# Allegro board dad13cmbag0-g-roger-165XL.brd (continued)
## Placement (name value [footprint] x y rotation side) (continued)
PR73  620k/f_4  [RC0402]  116.67 40.9 270 top
PR74  100k_4  [RC0402]  134.83 40.75 0 top
PR75  *0_4_nc  [RC0402]  118.2 40.39 180 top
PR76  *sj0805_nc  [SHORT0805]  163.03 40.21 270 top
PR77  100k/f_4  [RC0402]  125.05 40.09 180 top
PR78  0_6  [RC0603]  146.84 39.7 0 top
PR79  0_6  [RC0603]  155.86 39.7 180 top
PR80  147k/f_4  [RC0402]  137.55 38.94 270 top
PR81  17.4k/f_4  [RC0402]  128.56 38.56 90 top
PR82  *sj0402_nc  [SHORT0402]  115.28 38.36 90 top
PR83  *sj0402_nc  [SHORT0402]  116.29 38.36 270 top
PR84  10k/f_4  [RC0402]  192.19 37.34 270 top
PR86  *sj0402_nc  [SHORT0402]  125.94 35.89 90 top
PR87  *sj0402_nc  [SHORT0402]  126.96 35.89 90 top
PR88  35.7k/f_4  [RC0402]  128.99 35.89 270 top
PR89  220k/f_4  [RC0402]  131.02 35.89 90 top
PR90  71.5k/f_4  [RC0402]  115.78 35.82 180 top
PR91  *sj0603_nc  [SHORT0603]  122.97 35.51 270 top
PR92  *sj0603_nc  [SHORT0603]  149.18 34.75 270 top
PR93  11.5k/f_4  [RC0402]  191.65 34.5 0 top
PR94  *sj0402_nc  [SHORT0402]  164.91 34.24 90 top
PR95  *10k_4_nc  [RC0402]  165.92 34.09 90 top
PR96  10k_4  [RC0402]  168.11 34.24 90 top
PR98  12.4k/f_4  [RC0402]  132.42 34.12 180 top
PR100  4.02k/f_4  [RC0402]  124.29 33.35 0 top
PR101  10k/f_4  [RC0402]  191.65 33.33 180 top
PR102  10k/f_4  [RC0402]  132.42 33.1 0 top
PR103  20k/f_4  [RC0402]  113.8 33.08 0 top
PR104  0_6  [RC0603]  119.39 32.52 90 top
PR105  4.7k_4  [RC0402]  132.42 31.83 0 top
PR106  20k/f_4  [RC0402]  114.31 31.45 90 top
PR107  *sj0805_nc  [SHORT0805]  95.46 31.32 270 top
PR108  *2.2_8_nc  [RC0805]  140.65 31.14 270 top
PR109  *2.2_8_nc  [RC0805]  160.61 31.07 270 top
PR110  *sj0402_nc  [SHORT0402]  189.89 29.46 270 top
PR111  10k_4  [RC0402]  190.9 29.46 270 top
PR112  10k_4  [RC0402]  192.93 29.46 270 top
PR113  *sj0402_nc  [SHORT0402]  193.95 29.46 90 top
PR114  *10k_4_nc  [RC0402]  98.89 28.4 270 top
PR115  *sj0402_nc  [SHORT0402]  99.91 28.4 270 top
PR116  0_6  [RC0603]  127.31 27.18 90 top
PR117  *sj0805_nc  [SHORT0805]  92.8 27.13 0 top
PR118  *2.2_8_nc  [RC0805]  112.76 26.67 0 top
PR119  10_12  [RC1206]  131.56 25.61 270 top
PR120  *sj0402_nc  [SHORT0402]  198.59 23.45 0 top
PR121  4.02k/f_4  [RC0402]  120.61 19.77 90 top
PR123  *100k_4_nc  [RC0402]  198.59 22.43 0 top
PR124  10k_4  [RC0402]  9.23 23.07 90 top
PR125  *100k_4_nc  [RC0402]  198.59 18.37 0 top
PR127  *sj0805_nc  [SHORT0805]  173.82 18.11 180 top
PR128  *sj0402_nc  [SHORT0402]  198.59 17.35 0 top
PR129  *sj0805_nc  [SHORT0805]  165.95 16.84 0 top
PR130  200k_4  [RC0402]  133.36 16.49 180 top
PR131  *10k_4_nc  [RC0402]  10.25 23.07 90 top
PR132  2.2_8  [RC0805]  127.62 14.99 0 top
PR133  10k_4  [RC0402]  108.16 14.41 180 top
PR134  10k_4  [RC0402]  110.2 14.41 0 top
PR135  15k_4  [RC0402]  4.02 14.33 0 top
PR136  10k_4  [RC0402]  2.32 13.7 90 top
PR137  100k_4  [RC0402]  4.02 13.19 0 top
PR138  100_4  [RC0402]  112.23 12.91 270 top
PR139  100_4  [RC0402]  113.62 12.91 270 top
PR140  100_4  [RC0402]  107.66 12.88 270 top
PR141  100_4  [RC0402]  110.7 12.88 270 top
PR142  10k_4  [RC0402]  132.39 12.65 180 top
PR143  *sj0402_nc  [SHORT0402]  168.34 11.69 90 top
PR144  *10k_4_nc  [RC0402]  169.48 11.69 90 top
PR145  10k_4  [RC0402]  171.64 11.69 90 top
PR146  *sj0402_nc  [SHORT0402]  172.78 11.69 270 top
PR147  680k_4  [RC0402]  135.34 9.48 90 top
PR148  2.2k_4  [RC0402]  5.9 8.46 90 top
PR149  33_4  [RC0402]  4.33 8.44 180 top
PR150  100k_4  [RC0402]  133.66 7.14 180 top
PR151  47k_4  [RC0402]  157.31 65.23 270 bottom
PR152  240k_4  [RC0402]  158.33 65.23 90 bottom
PR155  5.76k/f_4  [RC0402]  28.28 63.33 270 bottom
PR156  *sj0402_nc  [SHORT0402]  183.25 63.17 180 bottom
PR157  *sj0201_nc  [SHORT0201]  88.12 62.31 90 bottom
PR158  *sj0201_nc  [SHORT0201]  89.06 62.31 90 bottom
PR160  10k/f_4  [RC0402]  28.79 61.8 180 bottom
PR161  300k/f_4  [RC0402]  186.9 61.55 270 bottom
PR162  *10k/f_4_nc  [RC0402]  188.05 61.55 90 bottom
PR163  *10k/f_4_nc  [RC0402]  189.19 61.55 90 bottom
PR164  10k/f_4  [RC0402]  190.33 61.55 90 bottom
PR165  10k/f_4  [RC0402]  21.68 61.42 90 bottom
PR166  *sj0402_nc  [SHORT0402]  24.98 61.42 270 bottom
PR167  *sj0402_nc  [SHORT0402]  26.12 61.42 270 bottom
PR168  *sj0603_nc  [SHORT0603]  109.79 61.35 0 bottom
PR169  10k/f_4  [RC0402]  19.64 60.79 0 bottom
PR170  2.49k/f_4  [RC0402]  28.79 59.77 180 bottom
PR171  0_6  [RC0603]  101.71 58.37 90 bottom
PR172  100k/ntc/b4250_4  [RC0402]  17.99 58.12 270 bottom
PR173  *sj0402_nc  [SHORT0402]  103.46 57.99 90 bottom
PR174  *sj0402_nc  [SHORT0402]  104.48 57.99 90 bottom
PR175  *0_4_nc  [RC0402]  105.5 57.99 270 bottom
PR176  2.2_6  [RC0603]  15.83 57.94 270 bottom
PR177  *562k/f_4_nc  [RC0402]  19.64 57.74 180 bottom
PR178  499k/f_4  [RC0402]  19.64 56.72 180 bottom
PR179  *sj0402_nc  [SHORT0402]  28.94 56.6 0 bottom
PR180  9.31k/f_4  [RC0402]  19.57 55.71 180 bottom
PR181  *sj0402_nc  [SHORT0402]  28.94 55.45 0 bottom
PR182  150k/f_4  [RC0402]  19.64 54.69 0 bottom
PR183  *sj0402_nc  [SHORT0402]  28.94 54.31 0 bottom
PR184  2.94k/f_4  [RC0402]  19.64 53.67 180 bottom
PR185  *sj0402_nc  [SHORT0402]  22.44 52.28 270 bottom
PR186  *sj0402_nc  [SHORT0402]  23.45 52.28 270 bottom
PR187  *0_4_nc  [RC0402]  24.47 52.4 90 bottom
PR188  1k_4  [RC0402]  25.49 52.4 90 bottom
PR189  *sj0402_nc  [SHORT0402]  27.52 52.4 270 bottom
PR190  130_4  [RC0402]  28.53 52.4 270 bottom
PR191  *sj0402_nc  [SHORT0402]  30.95 52.4 270 bottom
PR192  1.91k/f_4  [RC0402]  18.12 52.15 270 bottom
PR193  18.7k/f_4  [RC0402]  19.14 52.15 90 bottom
PR194  10k/ntc/b3900_4  [RC0402]  20.15 52.15 270 bottom
PR196  2.2_8  [RC0805]  8.87 45.5 0 bottom
PR198  *sj0402_nc  [SHORT0402]  94.73 33.48 90 bottom
PR199  *100k_4_nc  [RC0402]  95.74 33.48 90 bottom
PR202  *sj0402_nc  [SHORT0402]  105.24 31.2 90 bottom
PR204  100k/f_4  [RC0402]  152.11 26.01 0 bottom
PR207  137k/f_4  [RC0402]  147.91 25.35 90 bottom
PR208  1.5m_4  [RC0402]  155.28 24.72 180 bottom
PR210  0.01_0612  [RC3216-4P]  127.72 22.13 270 bottom
PR211  0.01_0612  [RC3216-4P]  122.56 14.1 0 bottom
PR212  *0_4_nc  [RC0402]  181.57 13.16 90 bottom
PR213  *sj0402_nc  [SHORT0402]  182.97 13.16 270 bottom
PR214  51.1k/f_4  [RC0402]  185.51 12.65 0 bottom
PR215  102k/f_4  [RC0402]  187.54 11.51 0 bottom
PR218  75k/f_4  [RC0402]  128.99 45.67 90 top
PR219  100k_4  [RC0402]  152.74 24.21 270 top
PR220  *0_4_nc  [RC0402]  7.33 22.56 0 top
PR221  *sj0402_nc  [SHORT0402]  177 65.28 180 top
PR222  100k_4  [RC0402]  6.18 16.59 270 top
PR223  *sj0402_nc  [SHORT0402]  177.25 66.35 180 top
PR224  *sj0402_nc  [SHORT0402]  176.74 64.27 180 top
PR225  *sj0402_nc  [SHORT0402]  178.78 66.63 90 top
PR226  *sj0402_nc  [SHORT0402]  46.82 65.99 180 top
PR227  *0_4_nc  [RC0402]  102.96 31.2 270 bottom
PR228  *sj0402_nc  [SHORT0402]  104.1 31.2 90 bottom
PR229  *sj0402_nc  [SHORT0402]  58 27.13 270 bottom
PR230  *sj0402_nc  [SHORT0402]  126.2 45.93 90 top
PR231  *100k_4_nc  [RC0402]  122.9 21.92 270 top
PR232  *sj0402_nc  [SHORT0402]  169.12 34.24 270 top
PU1  oz9955hln  [QFN24-4X4-5-25P-0_8H]  181.37 62.44 180 top
PU2  tps22966dpur  [SON14-3X2-4-15P]  99.65 50.25 0 top
PU3  tps22966dpur  [SON14-3X2-4-15P]  123.12 49.1 0 top
PU4  tps22965dsgr  [SON8-2X2-5-9P]  160.61 45.93 90 top
PU5  tps22966dpur  [SON14-3X2-4-15P]  190.33 44.66 0 top
PU6  azv331ktr-g1  [SOT23-5]  129.75 41.48 270 top
PU7  rt8230cgqw  [WQFN20-3X3-4-21P]  151.37 39.04 270 top
PU8  nl27wz00usg  [VSSOP8-3_1-5-8P-0_9H]  133.56 38.82 270 top
PU9  tps22966dpur  [SON14-3X2-4-15P]  166.31 37.78 0 top
PU10  rt8231agqw  [WQFN20-3X3-4-21P]  119.44 36.96 180 top
PU11  g9661-25adjtp1u  [TSOT23-6-2_8-95-6P-1H]  195.39 35.41 90 top
PU12  bq24715rgrr  [PVQFN20-3_5X3_5-5-25P]  128.25 31.68 90 top
PU13  tps22966dpur  [SON14-3X2-4-15P]  96.38 27.74 90 top
PU14  tps22966dpur  [SON14-3X2-4-15P]  191.31 26.1 180 top
PU15  tps22966dpur  [SON14-3X2-4-15P]  202.02 20.38 270 top
PU16  tps22966dpur  [SON14-3X2-4-15P]  170.54 15.37 0 top
PU17  tps51362rver  [QFN28-4_5X3_5-4-29P]  105.52 62.49 90 bottom
PU18  tps51622arsmr  [QFN32-4X4-4-42P-1H]  24.22 56.98 90 bottom
PU19  *tps22965dsgr_nc  [SON8-2X2-5-9P]  94.24 35.87 270 bottom
PU20  azv331ktr-g1  [SOT23-5]  152.26 23.65 180 bottom
PU21  rt8068azqw  [DFN10-3X3-5-11P-RT9296]  183.8 10.32 90 bottom
PV1  fbd13021010  [SPAD-RE95X87]  45.91 30.2 180 bottom
PV2  *fbkt200401_nc  [SPAD-RE95X87]  54.91 30.2 180 bottom
Q1  dmn5l06wk-7  [UMT_213-3-1_3]  205.57 65.49 270 top
Q2  2n7002w  [UMT_213-3-1_3]  198.21 65.36 90 top
Q3  2n7002w  [UMT_213-3-1_3]  144.36 64.98 270 top
Q4  dmn66d0ldw-7  [SOT-363]  128.86 61.17 270 top
Q5  2n7002w  [UMT_213-3-1_3]  122.51 55.2 270 top
Q6  mmst3904-7-f  [UMT_213-3-1_3]  55.2 51.77 0 top
Q7  2n7002w  [UMT_213-3-1_3]  21.57 40.09 180 top
Q8  2n7002w  [UMT_213-3-1_3]  79.72 35.23 180 top
Q9  ao3409  [SOT23_213-3_3-2]  79.59 31.7 90 top
Q13  2n7002w  [UMT_213-3-1_3]  180.43 24.72 270 top
Q14  2n7002w  [UMT_213-3-1_3]  159.06 22.03 270 top
Q15  lta014yubfs8tl  [UMT_213-3-1_3]  161.88 22.03 270 top
Q16  dmn66d0ldw-7  [SOT-363]  177.45 20.63 180 top
Q17  mmst3904-7-f  [UMT_213-3-1_3]  13.17 19.64 0 top
Q18  2n7002w  [UMT_213-3-1_3]  183.6 19.64 270 top
Q19  *ao3409_nc  [SOT23_213-3_3-2]  102.96 15.7 270 top
Q20  2n7002w  [UMT_213-3-1_3]  219.29 14.2 180 top
Q21  fdn357n  [SOT23_213-3_3-2]  177.23 13.59 180 top
Q22  *2n7002w_nc  [UMT_213-3-1_3]  99.27 13.16 90 top
Q23  2n7002w  [UMT_213-3-1_3]  42.61 65.87 180 bottom
Q24  *dmn66d0ldw-7_nc  [SOT-363]  91.53 55.45 180 bottom
Q25  dmn66d0ldw-7  [SOT-363]  91.53 53.17 0 bottom
Q26  dmn66d0ldw-7  [SOT-363]  172.17 46.31 180 bottom
Q27  dmn66d0ldw-7  [SOT-363]  178.75 45.67 0 bottom
Q28  dmn66d0ldw-7  [SOT-363]  89.62 44.15 270 bottom
Q29  2n7002w  [UMT_213-3-1_3]  94.09 42.09 270 bottom
Q30  mmst3904-7-f  [UMT_213-3-1_3]  206.33 34.24 90 top
Q31  2n7002w  [UMT_213-3-1_3]  221.42 28.78 90 bottom
Q32  *bss138_nc  [SOT23_213-3_3-2]  169.76 28.62 90 bottom
Q33  2n7002w  [UMT_213-3-1_3]  221.42 24.08 90 bottom
Q34  2n7002w  [UMT_213-3-1_3]  221.42 20.27 90 bottom
Q35  2n7002w  [UMT_213-3-1_3]  220.96 17.1 180 bottom
Q36  2n7002w  [UMT_213-3-1_3]  160.49 8.97 90 bottom
Q37  2n7002w  [UMT_213-3-1_3]  131.33 65.1 90 top
Q38  2n7002w  [UMT_213-3-1_3]  25.28 48.19 90 top
Q39  2n7002w  [UMT_213-3-1_3]  28.1 46.18 270 top
Q40  2n7002w  [UMT_213-3-1_3]  113.77 19.29 90 top
Q41  2n7002w  [UMT_213-3-1_3]  116.62 19.38 270 top
Q42  dmn66d0ldw-7  [SOT-363]  175.22 25.61 0 top
Q43  *dmn66d0ldw-7_nc  [SOT-363]  169.12 25.86 180 top
Q44  *dmn66d0ldw-7_nc  [SOT-363]  169.12 28.15 180 top
R1  150_6  [RC0603]  38.01 66.7 180 top
R2  8.25k/f_4  [RC0402]  70.44 60.02 0 top
R3  *0_4_nc  [RC0402]  207.48 66.25 270 top
R4  100k_4  [RC0402]  208.62 66.25 90 top
R6  10k_4  [RC0402]  140.55 65.82 270 top
R7  10k_4  [RC0402]  138.39 65.87 270 top
R8  1k_4  [RC0402]  172.55 65.49 0 top
R9  4.7k_4  [RC0402]  196.17 65.1 90 top
R10  1m_4  [RC0402]  200.24 65.1 90 top
R11  100k_4  [RC0402]  201.38 65.1 270 top
R12  *100k_4_nc  [RC0402]  202.52 65.1 90 top
R13  10k_4  [RC0402]  129.32 65.28 90 top
R14  1m_4  [RC0402]  203.67 64.72 90 top
R15  *sj0603_nc  [SHORT0603]  133.23 63.96 90 top
R16  *100k_4_nc  [RC0402]  140.55 63.78 270 top
R17  *100k_4_nc  [RC0402]  142.2 63.96 270 top
R18  *0_6_nc  [RC0603]  127.21 63.78 270 top
R19  10k_4  [RC0402]  137.88 63.58 270 top
R20  *sj0402_nc  [SHORT0402]  139.02 63.58 270 top
R21  10k_4  [RC0402]  125.62 62.97 0 top
R22  *0_4_nc  [RC0402]  158.4 63.2 180 top
R23  *sj0402_nc  [SHORT0402]  131.02 62.82 180 top
R25  3k/f_4  [RC0402]  59.65 62.69 180 top
R26  *sj0402_nc  [SHORT0402]  131.02 61.8 180 top
R27  *sj0402_nc  [SHORT0402]  59.65 61.68 0 top
R28  *10k_4_nc  [RC0402]  78.32 60.71 90 top
R30  43_4  [RC0402]  131.4 60.66 0 top
R31  *51/f_4_nc  [RC0402]  41.49 60.41 0 top
R32  100/f_4  [RC0402]  38.95 60.15 270 top
R33  100/f_4  [RC0402]  39.96 60.15 270 top
R34  *100k_4_nc  [RC0402]  76.79 60.15 180 top
R35  3k/f_4  [RC0402]  64.09 59.77 90 top
R36  100k_4  [RC0402]  82.13 59.52 180 top
R37  *sj0402_nc  [SHORT0402]  84.16 59.52 0 top
R38  *sj0402_nc  [SHORT0402]  41.49 59.39 0 top
R39  100k_4  [RC0402]  130.9 59.14 90 top
R40  24.9/f_4  [RC0402]  66.76 58.98 180 top
R41  100k_4  [RC0402]  122.9 57.61 0 top
R42  100k_4  [RC0402]  128.76 58.63 180 top
R43  *1k_4_nc  [RC0402]  82.13 58.5 180 top
R44  *1k_4_nc  [RC0402]  84.16 58.5 0 top
R45  51/f_4  [RC0402]  39.46 58.63 0 top
R46  51/f_4  [RC0402]  41.49 58.37 180 top
R47  10k_4  [RC0402]  120.86 58.4 0 top
R48  4.7k_4  [RC0402]  147.41 58.37 90 top
R49  *sj0402_nc  [SHORT0402]  148.42 58.37 90 top
R50  *sj0402_nc  [SHORT0402]  149.44 58.37 90 top
R51  *sj0402_nc  [SHORT0402]  151.47 58.37 90 top
R52  *sj0402_nc  [SHORT0402]  152.49 58.37 90 top
R53  *sj0402_nc  [SHORT0402]  154.52 58.37 90 top
R54  *sj0402_nc  [SHORT0402]  155.53 58.37 90 top
R55  *sj0402_nc  [SHORT0402]  157.57 58.37 90 top
R56  0_4  [RC0402]  158.58 58.37 90 top
R57  4.7k_4  [RC0402]  159.6 58.37 270 top
R58  *0_4_nc  [RC0402]  160.61 58.37 270 top
R59  100k_4  [RC0402]  194.27 58.25 180 top
R60  0_6  [RC0603]  87.97 57.48 180 top
R62  *sj0603_nc  [SHORT0603]  68.03 56.72 270 top
R63  *sj0603_nc  [SHORT0603]  69.17 56.72 270 top
R64  *0_6_nc  [RC0603]  87.97 56.21 180 top
R65  10k_4  [RC0402]  80.86 55.58 0 top
R66  20k/f_4  [RC0402]  144.61 55.2 180 top
R67  *sj0402_nc  [SHORT0402]  128.1 54.82 90 top
R68  *10k_4_nc  [RC0402]  78.7 54.56 180 top
R69  *sj0402_nc  [SHORT0402]  83.75 54.56 0 top
R71  *100k_4_nc  [RC0402]  201 54.44 180 top
R72  100k_4  [RC0402]  125.31 54.31 0 top
R73  12k/f_4  [RC0402]  144.61 54.18 0 top
R74  10k_4  [RC0402]  187.16 54.18 0 top
R75  *sj0402_nc  [SHORT0402]  126.96 53.8 270 top
R76  *sj0402_nc  [SHORT0402]  196.43 53.8 90 top
R77  *0_4_nc  [RC0402]  197.44 53.8 270 top
R78  10k_4  [RC0402]  78.7 53.55 180 top
R79  *0_4_nc  [RC0402]  83.75 53.55 0 top
R80  *sj0805_nc  [SHORT0805]  185 53.29 90 top
R81  100k_4  [RC0402]  201 53.29 0 top
R82  *sj0603_nc  [SHORT0603]  75.91 53.17 0 top
R83  *1k_4_nc  [RC0402]  37.04 53.04 0 top
R84  10k_4  [RC0402]  85.28 54.06 90 top
R85  *10k_4_nc  [RC0402]  78.22 52.53 180 top
R86  10k_4  [RC0402]  80.25 52.53 0 top
R87  *10k_4_nc  [RC0402]  84.39 52.53 180 top
R88  *1k_4_nc  [RC0402]  37.04 52.02 0 top
R89  100k_4  [RC0402]  118.45 52.02 270 top
R90  *sj0402_nc  [SHORT0402]  73.49 51.54 180 top
R91  10k_4  [RC0402]  78.22 51.52 180 top
R92  8.2k_4  [RC0402]  80.25 51.52 180 top
R93  100k_4  [RC0402]  84.39 51.52 180 top
R94  10k_4  [RC0402]  85.91 51.9 270 top
R95  *sj1206_nc  [SHORT1206]  65.87 50.75 90 top
R96  *1k_4_nc  [RC0402]  38.19 50.63 0 top
R97  10k_4  [RC0402]  78.22 50.5 180 top
R98  10k_4  [RC0402]  84.31 50.5 180 top
R99  *sj0402_nc  [SHORT0402]  134.45 49.86 270 top
R100  10k_4  [RC0402]  80.25 49.48 180 top
R101  1k_4  [RC0402]  38.19 49.36 0 top
R102  *47k_4_nc  [RC0402]  84.31 49.48 0 top
R103  *sj0402_nc  [SHORT0402]  86.34 49.36 180 top
R104  22.6k/f_4  [RC0402]  198.97 48.72 90 top
R105  78.7k/f_4  [RC0402]  199.98 48.72 90 top
R106  *10k_4_nc  [RC0402]  201 48.72 90 top
R107  1m_4  [RC0402]  76.03 48.47 0 top
R108  10k_4  [RC0402]  80.25 48.47 180 top
R109  *1k_4_nc  [RC0402]  36.31 47.76 0 top
R111  *0_4_nc  [RC0402]  156.98 47.71 180 top
R112  *51_4_nc  [RC0402]  34.2 47.65 180 top
R113  10k_4  [RC0402]  80.86 47.45 180 top
R114  10k_4  [RC0402]  84.31 47.32 180 top
R115  *10k_4_nc  [RC0402]  86.34 47.32 0 top
R116  10k_4  [RC0402]  75.65 46.94 270 top
R117  *1k_4_nc  [RC0402]  37.32 46.72 0 top
R118  *sj_4_nc  [SHORT0402]  80.86 46.44 180 top
R119  10k_4  [RC0402]  82.89 46.31 180 top
R120  *1k_4_nc  [RC0402]  74.1 46.18 180 top
R121  *15k_4_nc  [RC0402]  82.89 45.29 180 top
R122  *sj0603_nc  [SHORT0603]  87.08 45.42 90 top
R123  *0_6_nc  [RC0603]  79.21 45.29 0 top
R124  10k_4  [RC0402]  91.53 44.53 90 top
R125  10k_4  [RC0402]  195.16 44.53 180 top
R126  22.6/f_4  [RC0402]  73.62 44.4 90 top
R127  10k_4  [RC0402]  74.64 44.4 90 top
R128  *sj0603_nc  [SHORT0603]  79.21 44.15 0 top
R129  10k_4  [RC0402]  203.54 43.64 0 top
R130  *0_6_nc  [RC0603]  66.63 43.06 180 top
R131  10k_4  [RC0402]  76.92 43.01 180 top
R132  51_4  [RC0402]  37.58 42.98 270 top
R133  51_4  [RC0402]  38.59 42.98 270 top
R134  51_4  [RC0402]  39.61 42.98 270 top
R135  *1k_4_nc  [RC0402]  40.62 42.98 90 top
R136  10k/f_4  [RC0402]  14.92 42.91 180 top
R137  10k/f_4  [RC0402]  17.08 42.91 180 top
R138  33_4  [RC0402]  106 42.75 180 top
R139  22_4  [RC0402]  68.54 42.12 90 top
R140  49.9/f_4  [RC0402]  72.1 42.12 0 top
R141  10k_4  [RC0402]  74.38 41.61 0 top
R142  100k_4  [RC0402]  89.62 41.61 0 top
R143  10k_4  [RC0402]  75.91 41.36 90 top
R144  *10k_4_nc  [RC0402]  76.92 41.36 90 top
R145  *sj0402_nc  [SHORT0402]  77.94 41.36 90 top
R146  *0_6_nc  [RC0603]  104.35 41.36 270 top
R147  100k_4  [RC0402]  200.24 41.36 90 top
R148  49.9/f_4  [RC0402]  72.1 41.1 0 top
R149  200/f_4  [RC0402]  41.11 41.36 0 top
R150  *sj0603_nc  [SHORT0603]  102.68 40.97 90 top
R151  100/f_4  [RC0402]  38.59 40.95 270 top
R152  *sj0402_nc  [SHORT0402]  89.6 40.59 180 top
R153  1m_4  [RC0402]  109.81 40.47 0 top
R154  22_4  [RC0402]  70.06 40.16 180 top
R155  121/f_4  [RC0402]  41.11 40.34 0 top
R156  10k_4  [RC0402]  75.02 39.32 270 top
R157  *100k_4_nc  [RC0402]  76.03 39.32 270 top
R158  22_4  [RC0402]  68.54 39.07 90 top
R159  *0_6_nc  [RC0603]  183.47 38.05 0 top
R160  *sj0402_nc  [SHORT0402]  20.79 37.57 90 top
R161  47k_4  [RC0402]  21.8 37.57 90 top
R162  *100k_4_nc  [RC0402]  184.49 36.91 0 top
R163  100k_4  [RC0402]  74.13 36.53 270 top
R164  *0_4_nc  [RC0402]  156.96 35.72 90 top
R165  1m_4  [RC0402]  82.13 35.49 90 top
R166  100k_4  [RC0402]  71.71 34.5 270 top
R167  *0_4_nc  [RC0402]  72.73 34.5 90 top
R168  *sj0402_nc  [SHORT0402]  74.13 34.5 270 top
R169  10k_4  [RC0402]  101.31 35.01 180 top
R170  *10k_4_nc  [RC0402]  172.43 33.87 0 top
R171  *0_4_nc  [RC0402]  180.3 33.23 180 top
R172  *0_6_nc  [RC0603]  183.98 32.39 0 top
R173  *49.9k/f_4_nc  [RC0402]  180.3 32.17 0 top
R174  47_4  [RC0402]  101.31 31.91 0 top
R175  33_4  [RC0402]  70.09 31.88 0 top
R176  *sj0603_nc  [SHORT0603]  170.27 31.46 0 top
R177  *0_6_nc  [RC0603]  77.07 31.45 90 top
R178  33_4  [RC0402]  68.51 32.39 270 top
R179  20k/f_4  [RC0402]  72.73 31.35 90 top
R180  20k/f_4  [RC0402]  74.41 31.35 90 top
R181  *100k_4_nc  [RC0402]  184.62 31.25 0 top
R182  *1k_4_nc  [RC0402]  70.09 30.84 0 top
R183  10k_4  [RC0402]  172.81 30.69 180 top
R184  *49.9k/f_4_nc  [RC0402]  180.3 30.27 0 top
R185  *sj0603_nc  [SHORT0603]  177.63 30.01 180 top
R186  *49.9k/f_4_nc  [RC0402]  180.3 29.25 0 top
R187  *sj0402_nc  [SHORT0402]  168.23 32.08 270 top
R188  *sj0402_nc  [SHORT0402]  102.58 28.45 0 top
R189  *0_4_nc  [RC0402]  103.59 28.45 0 top
R190  *sj0402_nc  [SHORT0402]  104.61 28.45 0 top
R191  *100k_4_nc  [RC0402]  176.87 28.36 270 top
R192  *49.9k/f_4_nc  [RC0402]  180.3 28.24 0 top
R193  *0_4_nc  [RC0402]  168.49 30.31 180 top
R194  *sj0402_nc  [SHORT0402]  102.58 27.39 0 top
R195  *0_4_nc  [RC0402]  103.59 27.39 0 top
R196  *sj0402_nc  [SHORT0402]  104.61 27.39 0 top
R197  *sj0402_nc  [SHORT0402]  102.58 26.37 0 top
R198  *0_4_nc  [RC0402]  103.59 26.37 0 top
R199  *sj0402_nc  [SHORT0402]  104.61 26.37 0 top
R200  10k_4  [RC0402]  177.25 23.96 180 top
R201  *sj0805_nc  [SHORT0805]  195.16 25.61 270 top
R202  *sj0402_nc  [SHORT0402]  102.58 25.35 0 top
R203  *0_4_nc  [RC0402]  103.59 25.35 0 top
R204  *sj0402_nc  [SHORT0402]  104.61 25.35 0 top
R205  *0_4_nc  [RC0402]  183.09 25.1 180 top
R206  620_4  [RC0402]  222.59 25.1 90 top
R207  10k_4  [RC0402]  158.71 24.46 180 top
R208  150_4  [RC0402]  162.14 24.46 180 top
R209  *sj0402_nc  [SHORT0402]  102.58 24.34 0 top
R210  *0_4_nc  [RC0402]  103.59 24.34 0 top
R211  *sj0402_nc  [SHORT0402]  104.61 24.34 0 top
R212  100k_4  [RC0402]  183.09 24.08 180 top
R213  *0_4_nc  [RC0402]  177.76 25.99 90 top
R214  *sj0805_nc  [SHORT0805]  188.43 23.45 90 top
R215  10k_4  [RC0402]  183.09 23.07 180 top
R216  10k_4  [RC0402]  183.09 22.05 180 top
R217  620_4  [RC0402]  222.59 21.54 90 top
R218  *0_4_nc  [RC0402]  180.5 21.26 180 top
R219  *0_4_nc  [RC0402]  187.72 21.16 180 top
R220  *0_8_nc  [RC0805]  173.7 20.15 180 top
R221  *0_4_nc  [RC0402]  187.72 20.15 180 top
R222  *0_4_nc  [RC0402]  180.5 19.99 180 top
R223  100k_4  [RC0402]  190.33 19.89 90 top
R224  *0_4_nc  [RC0402]  187.72 19.13 180 top
R225  26.1/f_4  [RC0402]  35.19 19.23 180 top
R226  *0_8_nc  [RC0805]  165.95 18.93 0 top
R227  *0_4_nc  [RC0402]  187.72 18.11 180 top
R228  26.1/f_4  [RC0402]  35.19 18.22 180 top
R229  620_4  [RC0402]  222.59 17.99 90 top
R230  34.8/f_4  [RC0402]  85.3 14.05 270 top
R231  *0_4_nc  [RC0402]  187.72 17.1 180 top
R232  10k_4  [RC0402]  220.94 17.1 0 top
R233  26.1/f_4  [RC0402]  78.62 19.08 0 top
R234  26.1/f_4  [RC0402]  78.62 17.96 0 top
R235  34.8/f_4  [RC0402]  78.57 15.57 90 top
R236  34.8/f_4  [RC0402]  39.08 15.96 270 top
R237  240/f_4  [RC0402]  58.89 16.08 180 top
R238  *0_4_nc  [RC0402]  187.67 16.08 180 top
R239  34.8/f_4  [RC0402]  32.55 16.72 180 top
R240  *0_4_nc  [RC0402]  187.67 15.07 180 top
R241  620_4  [RC0402]  222.46 14.81 90 top
R242  240/f_4  [RC0402]  12.38 14.28 90 top
R243  620_4  [RC0402]  222.08 13.16 180 top
R244  30_4  [RC0402]  18.91 13.03 90 top
R245  *100k_4_nc  [RC0402]  102.96 13.03 0 top
R246  *100k_4_nc  [RC0402]  101.18 12.53 90 top
R247  30_4  [RC0402]  61.99 12.43 90 top
R248  240/f_4  [RC0402]  44.92 9.35 270 top
R249  240/f_4  [RC0402]  22.87 10.75 270 top
R250  240/f_4  [RC0402]  89.49 10.24 270 top
R251  240/f_4  [RC0402]  68.92 9.22 180 top
R252  240/f_4  [RC0402]  72.17 7.62 0 top
R253  1k_4  [RC0402]  46.16 67.01 0 bottom
R254  3k/f_4  [RC0402]  73.62 65.49 270 bottom
R255  10k_4  [RC0402]  39.35 66.25 90 bottom
R257  *0_4_nc  [RC0402]  151.72 65.87 180 bottom
R258  *0_4_nc  [RC0402]  51.01 65.74 270 bottom
R259  *0_4_nc  [RC0402]  52.03 65.74 270 bottom
R260  1m_4  [RC0402]  65.62 65.74 270 bottom
R261  10k_4  [RC0402]  44.94 65.49 90 bottom
R262  10k_4  [RC0402]  46.34 65.49 270 bottom
R263  *sj0402_nc  [SHORT0402]  74.64 65.49 90 bottom
R264  *sj0402_nc  [SHORT0402]  151.72 64.72 0 bottom
R265  *100k/f_4_nc  [RC0402]  83.14 59.26 180 bottom
R266  10k_4  [RC0402]  85.18 59.26 0 bottom
R267  *10k_4_nc  [RC0402]  87.97 58.12 180 bottom
R268  *10k_4_nc  [RC0402]  83.14 58.25 180 bottom
R269  10k_4  [RC0402]  87.97 59.14 180 bottom
R270  10k_4  [RC0402]  83.27 56.37 180 bottom
R271  *1k_4_nc  [RC0402]  90 58.12 180 bottom
R272  *1k_4_nc  [RC0402]  92.03 58.12 0 bottom
R273  10k_4  [RC0402]  87.97 57.1 0 bottom
R274  *10k_4_nc  [RC0402]  90 57.1 180 bottom
R275  *10k_4_nc  [RC0402]  92.03 57.1 180 bottom
R276  10k_4  [RC0402]  85.43 56.39 180 bottom
R277  10k_4  [RC0402]  85.18 58.25 180 bottom
R278  10k_4  [RC0402]  88.33 55.71 0 bottom
R279  56_4  [RC0402]  34.5 55.58 180 bottom
R280  100k_4  [RC0402]  85.43 55.38 180 bottom
R281  10k_4  [RC0402]  83.27 55.33 180 bottom
R282  62_4  [RC0402]  31.96 55.07 270 bottom
R283  *62_4_nc  [RC0402]  32.98 55.07 270 bottom
R284  43_4  [RC0402]  34.63 54.56 0 bottom
R285  *sj0603_nc  [SHORT0603]  98.89 54.56 90 bottom
R286  10k_4  [RC0402]  85.3 54.17 180 bottom
R287  10k_4  [RC0402]  83.27 54.11 180 bottom
R288  *75_4_nc  [RC0402]  33.61 53.55 0 bottom
R289  75_4  [RC0402]  32.09 53.04 270 bottom
R290  *130_4_nc  [RC0402]  35.14 53.04 90 bottom
R291  10k_4  [RC0402]  83.27 52.66 180 bottom
R292  10k_4  [RC0402]  85.3 52.66 180 bottom
R293  130_4  [RC0402]  33.61 52.53 180 bottom
R294  15_4  [RC0402]  82.28 51.52 180 top
R295  10k_4  [RC0402]  83.27 51.64 180 bottom
R296  *1k_4_nc  [RC0402]  85.3 51.64 180 bottom
R297  10k_4  [RC0402]  98.89 51.13 90 bottom
R298  49.9/f_4  [RC0402]  34.63 51.52 180 bottom
R299  15_4  [RC0402]  82.28 50.5 180 top
R300  *1k_4_nc  [RC0402]  32.29 50.8 0 bottom
R301  10k_4  [RC0402]  83.27 50.63 180 bottom
R302  10k_4  [RC0402]  85.3 50.63 0 bottom
R303  15_4  [RC0402]  84.31 48.47 180 top
R304  15_4  [RC0402]  82.28 52.53 180 top
R305  *100k_4_nc  [RC0402]  185.77 49.99 0 bottom
R306  *100k_4_nc  [RC0402]  187.8 49.99 180 bottom
R307  15_4  [RC0402]  82.28 48.47 180 top
R308  *sj0402_nc  [SHORT0402]  180.35 49.76 270 bottom
R309  *sj0402_nc  [SHORT0402]  181.47 49.76 270 bottom
R310  *47k_4_nc  [RC0402]  83.4 49.03 180 bottom
R311  *sj0402_nc  [SHORT0402]  85.43 49.05 180 bottom
R312  10k_4  [RC0402]  110.58 49.48 270 bottom
R313  15_4  [RC0402]  82.28 49.48 180 top
R314  *sj0402_nc  [SHORT0402]  91.65 48.09 0 bottom
R315  *0_4_nc  [RC0402]  93.69 48.09 180 bottom
R316  *0_4_nc  [RC0402]  172.3 47.96 0 bottom
R317  10k_4  [RC0402]  83.4 47.71 180 bottom
R318  10k_4  [RC0402]  89.62 47.71 180 bottom
R319  *0_4_nc  [RC0402]  85.62 47.69 0 bottom
R320  *0_4_nc  [RC0402]  178.78 47.32 0 bottom
R321  *sj0402_nc  [SHORT0402]  200.75 42.88 0 bottom
R322  2.2k_4  [RC0402]  83.4 46.69 180 bottom
R323  100k_4  [RC0402]  89.62 46.69 180 bottom
R324  *sj0402_nc  [SHORT0402]  87.49 46.66 180 bottom
R325  1k_4  [RC0402]  85.44 46.64 180 bottom
R326  10k_4  [RC0402]  92.03 46.18 0 bottom
R327  *sj0402_nc  [SHORT0402]  200.75 43.9 0 bottom
R328  2.2k_4  [RC0402]  83.4 45.55 180 bottom
R329  100k_4  [RC0402]  85.44 45.5 180 bottom
R330  10k_4  [RC0402]  191.98 44.71 0 bottom
R331  *0_4_nc  [RC0402]  172.3 44.53 180 bottom
R332  *10k_4_nc  [RC0402]  93.56 44.4 0 bottom
R333  *0_4_nc  [RC0402]  178.67 44.07 180 bottom
R334  *sj0402_nc  [SHORT0402]  202.63 46.68 0 bottom
R335  *sj0402_nc  [SHORT0402]  202.63 47.69 0 bottom
R336  *49.9k/f_4_nc  [RC0402]  173.44 44.02 270 top
R337  *49.9k/f_4_nc  [RC0402]  174.46 44.02 270 top
R338  *150k/f_4_nc  [RC0402]  175.47 44.02 270 top
R339  *49.9k/f_4_nc  [RC0402]  176.49 44.02 270 top
R340  *49.9k/f_4_nc  [RC0402]  177.51 44.02 270 top
R341  *49.9k/f_4_nc  [RC0402]  178.52 44.02 270 top
R342  10k_4  [RC0402]  89.62 41.36 180 bottom
R343  *15k_4_nc  [RC0402]  91.65 41.36 180 bottom
R344  *10k_4_nc  [RC0402]  95.97 41.23 270 bottom
R345  220k/f_4  [RC0402]  23.33 40.72 180 bottom
R346  *0_4_nc  [RC0402]  28.92 40.59 90 bottom
R347  10k_4  [RC0402]  89.62 40.34 180 bottom
R348  *10k_4_nc  [RC0402]  91.65 40.34 180 bottom
R349  10k_4  [RC0402]  93.81 39.7 0 bottom
R350  10k_4  [RC0402]  89.62 39.32 180 bottom
R351  *100k_4_nc  [RC0402]  89.62 38.31 180 bottom
R352  *0_4_nc  [RC0402]  170.01 38.18 180 bottom
R353  *sj0402_nc  [SHORT0402]  81.72 36.73 0 bottom
R354  49.9/f_4  [RC0402]  64.81 35.31 90 bottom
R355  49.9/f_4  [RC0402]  65.82 35.31 90 bottom
R356  470_4  [RC0402]  55.59 8.21 90 bottom
R357  1k_4  [RC0402]  71.26 34.5 270 bottom
R358  33_4  [RC0402]  72.27 34.5 270 bottom
R359  33_4  [RC0402]  73.37 34.5 90 bottom
R360  330k_4  [RC0402]  74.38 33.99 90 bottom
R361  *330k_4_nc  [RC0402]  75.4 33.74 270 bottom
R362  330k_4  [RC0402]  76.41 33.74 270 bottom
R363  *10k_4_nc  [RC0402]  77.43 33.99 90 bottom
R364  *sj0402_nc  [SHORT0402]  78.45 33.99 90 bottom
R365  1m_4  [RC0402]  79.46 34.5 270 bottom
R366  10m_4  [RC0402]  82.23 34.37 90 bottom
R367  *sj0603_nc  [SHORT0603]  214.4 34 90 bottom
R368  *sj0603_nc  [SHORT0603]  215.67 34 90 bottom
R369  10k_4  [RC0402]  168.11 31.2 180 bottom
R370  *100k_4_nc  [RC0402]  170.14 31.2 180 bottom
R371  10k_4  [RC0402]  219.54 28.91 90 bottom
R372  5.11/f_4  [RC0402]  29.3 27.64 0 bottom
R373  2.7/f_4  [RC0402]  54.32 27.64 0 bottom
R374  5.11/f_4  [RC0402]  74.25 27.26 180 bottom
R375  1.8k/f_4  [RC0402]  26.76 27.13 90 bottom
R376  1.8k/f_4  [RC0402]  27.77 27.13 270 bottom
R377  1.8k/f_4  [RC0402]  51.78 27.13 90 bottom
R378  1.8k/f_4  [RC0402]  52.79 27.13 270 bottom
R379  1.8k/f_4  [RC0402]  75.78 26.75 270 bottom
R380  1.8k/f_4  [RC0402]  76.79 26.75 90 bottom
R381  24.9/f_4  [RC0402]  29.3 26.62 0 bottom
R382  24.9/f_4  [RC0402]  54.32 26.62 0 bottom
R383  24.9/f_4  [RC0402]  74.25 26.24 180 bottom
R384  10k_4  [RC0402]  219.59 26.12 270 bottom
R385  *0_4_nc  [RC0402]  167.73 25.61 90 bottom
R386  *0_4_nc  [RC0402]  168.74 25.61 90 bottom
R387  10k_4  [RC0402]  219.54 21.54 270 bottom
R388  *sj0402_nc  [SHORT0402]  151.85 20.4 270 bottom
R389  *sj0402_nc  [SHORT0402]  154.52 20.4 270 bottom
R390  *sj0402_nc  [SHORT0402]  155.53 20.4 270 bottom
R391  100k_4  [RC0402]  169.12 20.4 90 bottom
R392  200k/f_4  [RC0402]  170.14 20.4 90 bottom
R393  240/f_4  [RC0402]  11.11 16.24 270 bottom
R394  10k_4  [RC0402]  219.42 15.07 0 bottom
R395  100k_4  [RC0402]  160.49 11.38 180 bottom
R396  240/f_4  [RC0402]  48.09 8.08 90 bottom
R397  240/f_4  [RC0402]  58.13 7.95 90 bottom
R398  240/f_4  [RC0402]  24.6 7.83 90 bottom
R399  240/f_4  [RC0402]  69.43 7.83 90 bottom
R400  240/f_4  [RC0402]  80.35 7.83 90 bottom
R401  240/f_4  [RC0402]  92.8 7.83 90 bottom
R402  240/f_4  [RC0402]  35.29 7.75 90 bottom
R403  240/f_4  [RC0402]  34.12 7.74 90 bottom
R404  *0_4_nc  [RC0402]  142.45 65.99 270 top
R405  0_4  [RC0402]  41.64 42.98 270 top
R406  *0_4_nc  [RC0402]  86.93 50.88 90 top
R407  100k_4  [RC0402]  24.95 45.72 180 top
R408  49.9/f_6  [RC0603]  28.08 48.65 0 top
R409  100k_4  [RC0402]  116.32 16.77 0 top
R410  49.9/f_6  [RC0603]  116.59 21.87 180 top
R411  34.8/f_4  [RC0402]  37.42 15.57 0 top
R412  34.8/f_4  [RC0402]  32.55 15.7 180 top
R413  34.8/f_4  [RC0402]  29.3 16.46 180 top
R414  34.8/f_4  [RC0402]  29.8 15.45 180 top
R415  34.8/f_4  [RC0402]  37.42 8.84 0 top
R416  34.8/f_4  [RC0402]  39.58 7.83 180 top
R417  34.8/f_4  [RC0402]  37.42 7.83 0 top
R418  34.8/f_4  [RC0402]  37.42 9.86 0 top
R419  34.8/f_4  [RC0402]  29.3 10.24 180 top
R420  34.8/f_4  [RC0402]  29.3 9.22 180 top
R421  34.8/f_4  [RC0402]  29.3 8.21 180 top
R422  34.8/f_4  [RC0402]  29.3 7.19 180 top
R423  34.8/f_4  [RC0402]  29.8 14.43 180 top
R424  34.8/f_4  [RC0402]  29.8 13.42 180 top
R425  34.8/f_4  [RC0402]  29.3 12.27 180 top
R426  34.8/f_4  [RC0402]  29.3 11.26 180 top
R427  34.8/f_4  [RC0402]  37.42 10.88 0 top
R428  34.8/f_4  [RC0402]  37.42 11.89 0 top
R429  34.8/f_4  [RC0402]  37.42 12.91 0 top
R430  34.8/f_4  [RC0402]  37.42 13.92 0 top
R431  34.8/f_4  [RC0402]  37.42 16.84 0 top
R432  34.8/f_4  [RC0402]  32.6 19.26 180 top
R433  34.8/f_4  [RC0402]  29.3 18.5 180 top
R434  34.8/f_4  [RC0402]  29.3 17.48 180 top
R435  34.8/f_4  [RC0402]  80.73 7.57 0 top
R436  34.8/f_4  [RC0402]  74.38 9.48 180 top
R437  34.8/f_4  [RC0402]  83.4 9.48 0 top
R438  34.8/f_4  [RC0402]  83.4 10.49 0 top
R439  34.8/f_4  [RC0402]  74.38 8.46 180 top
R440  34.8/f_4  [RC0402]  74.38 7.45 180 top
R441  34.8/f_4  [RC0402]  76.41 7.45 180 top
R442  34.8/f_4  [RC0402]  83.4 7.45 0 top
R443  34.8/f_4  [RC0402]  83.4 11.51 0 top
R444  34.8/f_4  [RC0402]  83.4 12.53 0 top
R445  34.8/f_4  [RC0402]  79.59 15.57 90 top
R446  34.8/f_4  [RC0402]  83.4 14.56 0 top
R447  34.8/f_4  [RC0402]  73.37 12.53 180 top
R448  34.8/f_4  [RC0402]  73.37 11.51 180 top
R449  34.8/f_4  [RC0402]  73.37 10.49 180 top
R450  34.8/f_4  [RC0402]  83.4 8.46 0 top
R451  34.8/f_4  [RC0402]  70.57 14.3 270 top
R452  34.8/f_4  [RC0402]  73.37 14.56 180 top
R453  34.8/f_4  [RC0402]  71.71 14.3 270 top
R454  34.8/f_4  [RC0402]  73.37 13.54 180 top
R455  34.8/f_4  [RC0402]  83.4 16.08 0 top
R456  34.8/f_4  [RC0402]  83.4 17.23 0 top
R457  34.8/f_4  [RC0402]  69.43 14.3 270 top
R458  34.8/f_4  [RC0402]  68.29 14.3 270 top
R459  *10k_4_nc  [RC0402]  96.73 56.98 0 bottom
R460  10k_4  [RC0402]  96.73 58.12 180 bottom
R461  *49.9k/f_4_nc  [RC0402]  172.43 44.02 270 top
R462  *sj0603_nc  [SHORT0603]  66.63 41.79 180 top
R463  *sj0603_nc  [SHORT0603]  107.27 40.09 180 bottom
R464  *0_4_nc  [RC0402]  100.92 33.48 270 top
R465  *sj0402_nc  [SHORT0402]  10.75 30.31 0 bottom
R471  *100k_4_nc  [RC0402]  103.21 19.51 0 top
R472  100k_4  [RC0402]  103.21 20.53 0 top
R473  *0_4_nc  [RC0402]  12.79 30.31 0 bottom
R474  *10k_4_nc  [RC0402]  161.38 39.45 270 top
R475  100k_4  [RC0402]  123.15 59.14 270 top
R476  10k_4  [RC0402]  78.95 43.01 180 top
R477  10k_4  [RC0402]  180.55 41.86 270 bottom
R478  *0_4_nc  [RC0402]  174.33 40.97 90 bottom
R479  *0_4_nc  [RC0402]  175.35 40.97 90 bottom
R480  *0_4_nc  [RC0402]  176.36 40.97 90 bottom
R481  *0_4_nc  [RC0402]  177.38 40.97 90 bottom
R482  *0_4_nc  [RC0402]  178.39 40.97 90 bottom
R483  *0_4_nc  [RC0402]  179.41 40.97 90 bottom
R484  10k_4  [RC0402]  172.17 24.46 90 top
R485  *10k_4_nc  [RC0402]  172.17 25.99 0 top
R486  *10k_4_nc  [RC0402]  172.17 27 0 top
R487  0_4  [RC0402]  177.99 28.35 90 top
RP1  2.2kx2  [4P2R-0404]  134.83 63.58 0 top
RP2  2.2kx2  [4P2R-0404]  136.48 63.58 0 top
RP3  2.2kx2  [4P2R-0404]  74.25 59.9 270 top
RP4  10kx2  [4P2R-0404]  80.86 53.93 90 top
RP5  2.2kx2  [4P2R-0404]  144.87 52.4 270 top
RP6  2.2kx2  [4P2R-0404]  89.49 44.76 270 top
RP7  10kx2  [4P2R-0404]  89.49 43.11 270 top
RP8  2.2kx2  [4P2R-0404]  91.53 40.97 180 top
RP9  1kx2  [4P2R-0404]  98.69 31.32 90 top
RP10  1kx2  [4P2R-0404]  154.9 21.16 90 top
RP11  10kx2  [4P2R-0404]  156.68 21.04 0 top
RP14  2.2kx2  [4P2R-0404]  175.47 16.21 270 top
RP25  10kx4  [8P4R-0402-SMT]  53.93 65.74 180 bottom
RP26  10kx2  [4P2R-0404]  94.57 57.23 90 bottom
RP27  1kx2  [4P2R-0404]  94.62 55.45 270 bottom
RP28  0x4  [8P4R-0402-SMT]  104.99 54.44 180 bottom
RP29  1kx2  [4P2R-0404]  94.32 53.17 270 bottom
RP30  10kx2  [4P2R-0404]  88.22 52.79 90 bottom
RP31  10kx4  [8P4R-0402-SMT]  90.64 50.37 90 bottom
RP32  2.2kx2  [4P2R-0404]  175.22 46.31 270 bottom
RP33  10kx2  [4P2R-0404]  183.73 41.86 180 bottom
RP34  10kx2  [4P2R-0404]  182.08 41.86 180 bottom
RP35  10kx2  [4P2R-0404]  174.84 43.39 180 bottom
RP36  10kx2  [4P2R-0404]  176.62 43.39 180 bottom
RT1  10k/ntc_4  [RC0402]  172.55 64.47 0 top
RTCBT1  aaa-bat-046-k03  [BAT-AP-AAA-BAT-046-2P]  215.2 23.9 270 top
RTCR1  5.1k/f_4  [RC0402]  205.32 36.78 180 top
RTCR2  12k/f_4  [RC0402]  206.97 37.16 270 top
RTCR3  *sj0402_nc  [SHORT0402]  209.89 31.07 180 top
RTCR4  1.05k/f_4  [RC0402]  209.89 32.08 180 top
SJ1  *sj0402_nc  [SHORT0402]  26.27 58.02 90 top
SJ2  *sj0402_nc  [SHORT0402]  138.01 28.02 90 top
SJ3  *sj0402_nc  [SHORT0402]  165.16 26.55 90 top
SJ4  *sj0402_nc  [SHORT0402]  164.09 26.52 90 top
SJ5  *sj0402_nc  [SHORT0402]  126.53 32.14 270 bottom
SW1  mptcf-t-q-t/r(619)  [SW-SKRELJE010-2P-SMT]  222.6 31.9 90 top
TP2  *pad_nc  [TP2650]  79.21 63.45 0 top
TP5  *pad_nc  [TP2650]  71.16 59.01 0 top
TP6  *pad_nc  [TP2650]  76.79 58.12 0 top
TP7  *pad_nc  [TP2650]  76.79 56.72 0 top
TP8  *pad_nc  [TP2650]  37.93 56.6 0 top
TP9  *pad_nc  [TP2650]  39.2 56.6 0 top
TP11  *pad_nc  [TP2650]  36.66 55.33 0 top
TP12  *pad_nc  [TP2650]  37.93 55.33 0 top
TP13  *pad_nc  [TP2650]  66.57 55.42 0 top
TP14  *pad_nc  [TP2650]  36.66 54.06 0 top
TP15  *pad_nc  [TP2650]  65.14 54.13 0 top
TP16  *pad_nc  [TP2650]  66.68 54.09 0 top
TP17  *pad_nc  [TP2650]  196.4 51.72 0 top
TP18  *pad_nc  [TP2650]  34.25 51.39 0 top
TP19  *pad_nc  [TP2650]  36.15 51.03 0 top
TP20  *pad_nc  [TP2650]  32.47 50.88 0 top
TP21  *pad_nc  [TP2650]  85.73 50.32 0 top
TP22  *pad_nc  [TP2650]  77.61 49.59 0 top
TP23  *pad_nc  [TP2650]  77.45 48.26 0 top
TP24  *pad_nc  [TP2650]  78.85 48.04 0 top
TP25  *pad_nc  [TP2650]  66.38 47.2 0 top
TP26  *pad_nc  [TP2650]  67.65 47.2 0 top
TP27  *pad_nc  [TP2650]  77.81 46.94 0 top
TP28  *pad_nc  [TP2650]  54.22 46.22 0 top
TP29  *pad_nc  [TP2650]  72.63 45.93 0 top
TP30  *pad_nc  [TP2650]  64.35 45.8 0 top
TP31  *pad_nc  [TP2650]  76.29 45.42 0 top
TP32  *pad_nc  [TP2650]  81.49 45.27 0 top
TP33  *pad_nc  [TP2650]  76.01 44 0 top
TP34  *pad_nc  [TP2650]  88.02 43.39 0 top
TP36  *pad_nc  [TP2650]  74.76 42.75 0 top
TP37  *pad_nc  [TP2650]  125.44 34.47 0 top
TP38  *pad_nc  [TP2650]  142.71 33.99 0 top
TP39  *pad_nc  [TP2650]  155.59 29.3 0 top
TP40  *pad_nc  [TP2650]  117.18 29.29 0 top
TP41  *pad_nc  [TP2650]  143.09 29.24 0 top
TP42  *pad_nc  [TP2650]  181.29 27.16 0 top
TP43  *pad_nc  [TP2650]  118.58 27.51 0 top
TP44  *pad_nc  [TP2650]  179.99 27.16 0 top
TP45  *pad_nc  [TP2650]  183.58 26.7 0 top
TP46  *pad_nc  [TP2650]  126.15 21.32 0 top
TP47  *pad_nc  [TP2650]  129.65 17.56 0 top
TP48  *pad_nc  [TP2650]  73.87 68.28 180 bottom
TP49  *pad_nc  [TP2650]  52.31 67.16 180 bottom
TP50  *pad_nc  [TP2650]  37.07 67.24 180 bottom
TP51  *pad_nc  [TP2650]  40.27 67.01 180 bottom
TP53  *pad_nc  [TP2650]  55.71 66.5 180 bottom
TP54  *pad_nc  [TP2650]  47.3 66.12 180 bottom
TP57  *pad_nc  [TP2650]  37.22 65.97 180 bottom
TP58  *pad_nc  [TP2650]  38.44 65.56 180 bottom
TP59  *pad_nc  [TP2650]  47.3 64.85 180 bottom
TP62  *pad_nc  [TP2650]  55.71 65.18 180 bottom
TP63  *pad_nc  [TP2650]  206.59 64.98 180 bottom
TP64  *pad_nc  [TP2650]  206.59 63.58 180 bottom
TP65  *pad_nc  [TP2650]  30.44 60.79 180 bottom
TP66  *pad_nc  [TP2650]  31.73 59.72 180 bottom
TP67  *pad_nc  [TP2650]  30.44 59.49 180 bottom
TP68  *pad_nc  [TP2650]  33.23 59.47 180 bottom
TP69  *pad_nc  [TP2650]  35.57 59.62 180 bottom
TP70  *pad_nc  [TP2650]  30.9 58.25 180 bottom
TP71  *pad_nc  [TP2650]  33.89 58.23 180 bottom
TP72  *pad_nc  [TP2650]  32.34 58.2 180 bottom
TP73  *pad_nc  [TP2650]  35.11 57.43 180 bottom
TP74  *pad_nc  [TP2650]  30.57 56.6 180 bottom
TP75  *pad_nc  [TP2650]  31.84 56.6 180 bottom
TP76  *pad_nc  [TP2650]  33.11 56.6 180 bottom
TP77  *pad_nc  [TP2650]  81.85 56.01 180 bottom
TP78  *pad_nc  [TP2650]  30.57 55.33 180 bottom
TP79  *pad_nc  [TP2650]  86.83 54.61 180 bottom
TP80  *pad_nc  [TP2650]  81.85 54.51 180 bottom
TP81  *pad_nc  [TP2650]  30.57 54.06 180 bottom
TP82  *pad_nc  [TP2650]  36.28 53.8 180 bottom
TP83  *pad_nc  [TP2650]  81.85 53.24 180 bottom
TP84  *pad_nc  [TP2650]  86.8 53.04 180 bottom
TP85  *pad_nc  [TP2650]  36.28 52.4 180 bottom
TP86  *pad_nc  [TP2650]  81.11 52.2 180 bottom
TP87  *pad_nc  [TP2650]  87.72 51.64 180 bottom
TP88  *pad_nc  [TP2650]  81.85 51.16 180 bottom
TP89  *pad_nc  [TP2650]  88.86 50.88 180 bottom
TP90  *pad_nc  [TP2650]  35.01 50.53 180 bottom
TP91  *pad_nc  [TP2650]  36.28 50.53 180 bottom
TP92  *pad_nc  [TP2650]  33.74 50.5 180 bottom
TP93  *pad_nc  [TP2650]  86.73 50.22 180 bottom
TP94  *pad_nc  [TP2650]  81.11 50.12 180 bottom
TP95  *pad_nc  [TP2650]  193.33 49.97 180 bottom
TP96  *pad_nc  [TP2650]  87.97 49.94 180 bottom
TP97  *pad_nc  [TP2650]  32.47 49.1 180 bottom
TP98  *pad_nc  [TP2650]  33.74 49.1 180 bottom
TP99  *pad_nc  [TP2650]  35.01 49.1 180 bottom
TP100  *pad_nc  [TP2650]  36.28 49.1 180 bottom
TP101  *pad_nc  [TP2650]  81.11 48.85 180 bottom
TP102  *pad_nc  [TP2650]  32.5 47.65 180 bottom
TP103  *pad_nc  [TP2650]  33.77 47.65 180 bottom
TP104  *pad_nc  [TP2650]  35.04 47.65 180 bottom
TP105  *pad_nc  [TP2650]  36.33 47.63 180 bottom
TP106  *pad_nc  [TP2650]  81.11 47.58 180 bottom
TP107  *pad_nc  [TP2650]  87.08 47.58 180 bottom
TP109  *pad_nc  [TP2650]  35.39 46.33 180 bottom
TP110  *pad_nc  [TP2650]  33.61 46.31 180 bottom
TP111  *pad_nc  [TP2650]  88.15 45.57 180 bottom
TP112  *pad_nc  [TP2650]  93.38 45.34 180 bottom
TP113  *pad_nc  [TP2650]  31.71 45.19 0 bottom
TP114  *pad_nc  [TP2650]  32.98 45.17 180 bottom
TP115  *pad_nc  [TP2650]  34.25 45.17 180 bottom
TP117  *pad_nc  [TP2650]  86.95 44.91 180 bottom
TP118  *pad_nc  [TP2650]  96.12 42.75 180 bottom
TP119  *pad_nc  [TP2650]  87.97 41.61 180 bottom
TP120  *pad_nc  [TP2650]  87.97 40.34 180 bottom
TP121  *pad_nc  [TP2650]  180.81 40.34 180 bottom
TP122  *pad_nc  [TP2650]  182.08 39.96 180 bottom
TP123  *pad_nc  [TP2650]  87.97 38.56 180 bottom
TP124  *pad_nc  [TP2650]  49.11 37.04 180 bottom
TP125  *pad_nc  [TP2650]  50.51 37.04 180 bottom
TP126  *pad_nc  [TP2650]  52.71 37.04 180 bottom
TP127  *pad_nc  [TP2650]  53.98 37.04 180 bottom
TP128  *pad_nc  [TP2650]  61.05 37.04 180 bottom
TP129  *pad_nc  [TP2650]  62.32 37.04 180 bottom
TP130  *pad_nc  [TP2650]  83.14 36.81 180 bottom
TP131  *pad_nc  [TP2650]  34.25 36.53 180 bottom
TP132  *pad_nc  [TP2650]  35.52 36.53 180 bottom
TP133  *pad_nc  [TP2650]  57.03 36.28 180 bottom
TP134  *pad_nc  [TP2650]  58.28 35.77 180 bottom
TP135  *pad_nc  [TP2650]  82.28 35.77 180 bottom
TP136  *pad_nc  [TP2650]  59.57 35.74 180 bottom
TP137  *pad_nc  [TP2650]  154.7 37.22 0 top
TP138  *pad_nc  [TP2650]  81.11 35.26 180 bottom
TP141  *pad_nc  [TP2650]  16.3 31.09 180 bottom
TP142  *pad_nc  [TP2650]  145.25 15.96 180 bottom
TP143  *pad_nc  [TP2650]  145.88 10.62 180 bottom
TP144  *pad_nc  [TP2650]  145.76 7.83 180 bottom
TP145  *pad_nc  [TP2650]  82.31 53.67 0 top
U1  *tc7sh08fu_nc  [SSOP5-P-A-TOSHIBA-B]  156.55 60.91 90 top
U2  sn74cbtd3306cpwr  [TSSOP8-6_4-65]  198.08 59.39 180 top
U3  sn74cbtd3306cpwr  [TSSOP8-6_4-65]  201.51 59.39 180 top
U4  it8587vg/fx  [BGA128-ITE-IT8528VGAX]  138.01 56.98 0 top
U5  g5243a  [SOT23-5]  186.27 56.85 270 top
U6  at97sc3204-x2a1d-ab  [TSSOP28-6_4-65-1_2H]  152.74 52.53 0 top
U7  tps2546rter  [QFN16-3X3-5-17P-TPS2546RTER]  199.81 45.09 0 top
U8  emc1423-1-aizl-tr  [TSSOP10-4_9-5]  15.91 40.75 270 top
U9  *tc7sh08fu_nc  [SSOP5-P-A-TOSHIBA-B]  89.88 38.69 90 top
U10  alc5505-cg  [QFN48-7X7-5-49P-ALC5505-CG]  106.94 35.11 180 top
U11  *txb0104rutr_nc  [UQFN12-2X1_7-4]  183.35 34.71 270 top
U12  *74ahc1g09gw_nc  [SOT353-1-2_125-65-5P]  173.57 32.3 0 top
U13  *txb0104rutr_nc  [UQFN12-2X1_7-4]  183.86 29.13 270 top
U14  *tc7sh08fu_nc  [SSOP5-P-A-TOSHIBA-B]  174.46 28.87 90 top
U15  w25q64fvssiq  [SOIC8-7_9-1_27-2_16H]  104.73 50.5 270 bottom
U16  hsw_ult_ddr3l/bga  [BGA1168-INTEL-HASWELL]  58.7 50.4 0 bottom
U17  74aup1g07gw  [SOT353-1-2_125-65-5P]  26.38 41.36 0 bottom
U18  memory-down_ddr3l  [BGA96-MICRON-MT41K512M16]  17.61 16.97 180 bottom
U19  memory-down_ddr3l  [BGA96-MICRON-MT41K512M16]  28.79 16.97 180 bottom
U20  memory-down_ddr3l  [BGA96-MICRON-MT41K512M16]  39.96 16.97 180 bottom
U21  memory-down_ddr3l  [BGA96-MICRON-MT41K512M16]  51.14 16.97 180 bottom
U22  memory-down_ddr3l  [BGA96-MICRON-MT41K512M16]  61.43 16.97 180 bottom
U23  memory-down_ddr3l  [BGA96-MICRON-MT41K512M16]  72.6 16.97 180 bottom
U24  memory-down_ddr3l  [BGA96-MICRON-MT41K512M16]  83.78 16.97 180 bottom
U25  memory-down_ddr3l  [BGA96-MICRON-MT41K512M16]  94.96 16.97 180 bottom
Y1  24mhz  [XTL-3_2X2_5-2_2X1_7-0_8H]  109.92 44.28 270 top
Y2  24mhz  [XTL-3_2X2_5-2_2X1_7-0_8H]  61.05 65.99 0 bottom
Y3  32.768khz  [XTAL-8_4X3_7-5_5X2_8]  87.97 34.62 0 bottom

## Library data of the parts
C1 C12 C21-C25 C27-C35 C46 C48-C50 C52 C57 C59 C62 C65 C70 C72 C73 C75 C76 C80 C84 C85 C88 C92 C97 C98 C114-C118 C123 C136 C141 C142 C148 C152-C155 C182 C196 C200 C205 C209 C239 C246 C258 C263-C266 C282-C284 C286 C291 C293 C297 C298 C302 C308 C311 C312 PC58 PC59 PC62 PC72 PC74-PC76 PC80 PC81 PC95 PC96 PC123 PC136-PC140 PC144 PC157 PC166-PC169 PC171-PC174 PC206 PC208 PC214 PC215 PC217 = CC0603
C2 C11 C51 C66 C81 C93 C127 C238 PC131 PC133 PC134 PC148 PC149 PC159 PC182-PC185 PC187 PC188 PC196 PC202 PC212 PC213 PC219 = CC0805
C3-C10 C13-C20 C26 C36-C45 C47 C53-C56 C58 C60 C61 C63 C64 C67-C69 C71 C74 C77-C79 C82 C83 C86 C89-C91 C94-C96 C99-C109 C111-C113 C119-C122 C124-C126 C128-C135 C137-C140 C143-C147 C149-C151 C156-C181 C183-C195 C197-C199 C201-C204 C206-C208 C210-C237 C240-C245 C247-C257 C259 C261 C262 C267 C268 C270-C281 C285 C287-C290 C292 C294-C296 C299-C301 C303-C307 C309 C310 C313 C525-C527 EC1-EC17 EC21-EC27 EC50-EC66 EC68-EC80 PC1-PC57 PC60 PC61 PC63-PC71 PC73 PC77-PC79 PC82-PC94 PC97-PC122 PC124-PC130 PC141-PC143 PC145-PC147 PC150-PC156 PC158 PC160 PC162 PC163 PC170 PC175-PC180 PC189 PC191-PC195 PC197-PC201 PC203-PC205 PC207 PC209-PC211 PC216 PC218 = CC0402
C87 C110 = CC3216-0_9H
C260 C269 PC132 PC135 PC181 PC186 PC190 = CC3528
CN1 = DP-3V112M1-RC5AA1-7H-20P
CN2 = USB-YUSB0011-P001A-10P
CN3 = YEA-BTB-055-P01-54P-LDH-SMT
CN4 = MINIPCI-SM3ZS067U215AE-75P-KE
CN5 = 88266-0200-2P-L
CN6 = 88513-0601-6P-L-SMT
CN7 = 50278-0050N-001-5P-L
CON1 = MIPCI-800055FB052GX00PL-52P-SMT
D1 D4 D6 D8 D10-D16 PD4 PD5 PD7 PD9 = DSMV
D2 D3 D5 D7 D9 D18 D24 D25 PD2 PD3 PD6 PQ3 PQ8 PQ10-PQ13 PQ18 PQ31 PQ32 Q1-Q3 Q5-Q8 Q13-Q15 Q17 Q18 Q20 Q22 Q23 Q29-Q31 Q33-Q41 = UMT_213-3-1_3
D19-D23 = LEDLTW-270TLA
DPF1 = F-3_2X1_65-3_68
EC18-EC20 EC28-EC49 = CC0201
EL1-EL4 EL6 EL8 EL9 = CHOKE-DLP11SN900HL2L-4P-1
ESD1-ESD3 = TSOP6-2_8-95
EU1 = UDFN10-2_5X1-5
FL1 L1 L2 L4 L5 PR19 PR27 PR78 PR79 PR104 PR116 PR171 PR176 R1 R18 R60 R64 R123 R130 R146 R159 R172 R177 R408 R410 = RC0603
FL2 L6-L11 PR8 PR56 PR108 PR109 PR118 PR132 PR196 R220 R226 = RC0805
FS1 = FSMD1206P150TS
H1 = H-TC166BC177IC131D91P2
H2 = H-C79D79N
H3 H10 = H-TC197BC220IC131D91P2
H4 = H-TC217BC197D102P2
H5-H7 = H-TC217IC142BC197D102P2
H8 = H-C217IC142D102PT
H9 = H-TIC217BC220D91P2
H11 = H-O79X87D79X87N
H12 = H-C220D142P2
H13 = H-TC217BC197IC142D102P2
H14 = PAD-M14-1
J1 = GS12401-1011-40P-R-NH-SMT
J2 = 91504-0401-4P-L
JBAT1 = GS73091-10272-7H-9P-LUV_AB
JKB1 = 50699-03001-001-30P-L
JP1 = 88513-0801-8P-L
JP2 = 88460-08XX-8P-L
L3 = L3_2X2_5-1_55
PC161 PC164 = CC3_5X1_7
PC165 = CC7343
PD1 = SOT363-2_1-65-6P
PD8 = D-SOD-123FL-2_8X1_8
PL1 PL4-PL7 = CHOKE-MPLC0730L3R3
PL2 = CHOKE-A915AY-H-100M
PL3 = CHOKE-PCMC063T-R82MN-4P-SMT
PL8 = CHOKE-PCMB053T-1R0MS
PQ1 PQ2 PQ6 PQ7 PQ14 Q4 Q16 Q24-Q28 Q42-Q44 = SOT-363
PQ4 PQ15 PQ17 Q9 Q19 Q21 Q32 = SOT23_213-3_3-2
PQ5 = SSOT6-2_8-95
PQ9 PQ20-PQ30 = PG-TSDSON-8-8P-R
PQ16 = SOT23_123-2_37-1_9-1_11H
PQ19 = SON8-4_5X3_5-5-9P
PR1 PR6 PR7 PR9-PR18 PR20-PR22 PR24-PR26 PR31 PR33 PR36 PR37 PR39 PR41 PR42 PR44 PR45 PR47 PR49 PR51 PR53-PR55 PR57-PR59 PR61-PR63 PR68 PR69 PR71-PR75 PR77 PR80 PR81 PR84 PR88-PR90 PR93 PR95 PR96 PR98 PR100-PR103 PR105 PR106 PR111 PR112 PR114 PR121 PR123-PR125 PR130 PR131 PR133-PR142 PR144 PR145 PR147-PR152 PR155 PR160-PR165 PR169 PR170 PR172 PR175 PR177 PR178 PR180 PR182 PR184 PR187 PR188 PR190 PR192-PR194 PR199 PR204 PR207 PR208 PR212 PR214 PR215 PR218-PR220 PR222 PR227 PR231 R2-R4 R6-R14 R16 R17 R19 R21 R22 R25 R28 R30-R36 R39-R48 R56-R59 R65 R66 R68 R71-R74 R77-R79 R81 R83-R89 R91-R94 R96-R98 R100-R102 R104-R109 R111-R117 R119-R121 R124-R127 R129 R131-R144 R147-R149 R151 R153-R158 R161-R167 R169-R171 R173-R175 R178-R184 R186 R189 R191-R193 R195 R198 R200 R203 R205-R208 R210 R212 R213 R215-R219 R221-R225 R227-R255 R257-R262 R265-R284 R286-R307 R310 R312 R313 R315-R320 R322 R323 R325 R326 R328-R333 R336-R352 R354-R363 R365 R366 R369-R387 R391-R407 R409 R411-R461 R464 R471-R487 RT1 RTCR1 RTCR2 RTCR4 = RC0402
PR2-PR5 PR32 PR38 PR40 PR48 PR50 PR52 PR66 PR67 PR70 PR82 PR83 PR86 PR87 PR94 PR110 PR113 PR115 PR120 PR128 PR143 PR146 PR156 PR166 PR167 PR173 PR174 PR179 PR181 PR183 PR185 PR186 PR189 PR191 PR198 PR202 PR213 PR221 PR223-PR226 PR228-PR230 PR232 R20 R23 R26 R27 R37 R38 R49-R55 R67 R69 R75 R76 R90 R99 R103 R118 R145 R152 R160 R168 R187 R188 R190 R194 R196 R197 R199 R202 R204 R209 R211 R263 R264 R308 R309 R311 R314 R321 R324 R327 R334 R335 R353 R364 R388-R390 R465 RTCR3 SJ1-SJ5 = SHORT0402
PR34 PR35 PR65 PR76 PR107 PR117 PR127 PR129 R80 R201 R214 = SHORT0805
PR46 PR91 PR92 PR168 R15 R62 R63 R82 R122 R128 R150 R176 R185 R285 R367 R368 R462 R463 = SHORT0603
PR119 = RC1206
PR157 PR158 = SHORT0201
PR210 PR211 = RC3216-4P
PU1 = QFN24-4X4-5-25P-0_8H
PU2 PU3 PU5 PU9 PU13-PU16 = SON14-3X2-4-15P
PU4 PU19 = SON8-2X2-5-9P
PU6 PU20 U5 = SOT23-5
PU7 PU10 = WQFN20-3X3-4-21P
PU8 = VSSOP8-3_1-5-8P-0_9H
PU11 = TSOT23-6-2_8-95-6P-1H
PU12 = PVQFN20-3_5X3_5-5-25P
PU17 = QFN28-4_5X3_5-4-29P
PU18 = QFN32-4X4-4-42P-1H
PU21 = DFN10-3X3-5-11P-RT9296
PV1 PV2 = SPAD-RE95X87
R95 = SHORT1206
RP1-RP11 RP14 RP26 RP27 RP29 RP30 RP32-RP36 = 4P2R-0404
RP25 RP28 RP31 = 8P4R-0402-SMT
RTCBT1 = BAT-AP-AAA-BAT-046-2P
SW1 = SW-SKRELJE010-2P-SMT
TP2 TP5-TP9 TP11-TP34 TP36-TP51 TP53 TP54 TP57-TP59 TP62-TP107 TP109-TP115 TP117-TP138 TP141-TP145 = TP2650
U1 U9 U14 = SSOP5-P-A-TOSHIBA-B
U2 U3 = TSSOP8-6_4-65
U4 = BGA128-ITE-IT8528VGAX
U6 = TSSOP28-6_4-65-1_2H
U7 = QFN16-3X3-5-17P-TPS2546RTER
U8 = TSSOP10-4_9-5
U10 = QFN48-7X7-5-49P-ALC5505-CG
U11 U13 = UQFN12-2X1_7-4
U12 U17 = SOT353-1-2_125-65-5P
U15 = SOIC8-7_9-1_27-2_16H
U16 = BGA1168-INTEL-HASWELL
U18-U25 = BGA96-MICRON-MT41K512M16
Y1 Y2 = XTL-3_2X2_5-2_2X1_7-0_8H
Y3 = XTAL-8_4X3_7-5_5X2_8

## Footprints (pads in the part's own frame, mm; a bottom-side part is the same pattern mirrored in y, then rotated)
4P2R-0404
  rect 0.33x0.762 smd: 1(-0.325,-0.5) 2(-0.325,0.5) 3(0.325,-0.5) 4(0.325,0.5)
8P4R-0402-SMT
  rect 0.406x0.61 smd: 1(-0.825,-0.45) 2(-0.825,0.45) 7(0.825,-0.45) 8(0.825,0.45)
  rect 0.254x0.61 smd: 3(-0.25,-0.45) 4(-0.25,0.45) 5(0.25,-0.45) 6(0.25,0.45)
50278-0050N-001-5P-L
  rect 0.787x1.905 smd: 1(-2.5,4.925) 2(-1.25,4.925) 3(0,4.925) 4(1.25,4.925) 5(2.5,4.925)
  rect 1.295x3.353 smd: 6(-5.35,0) 7(5.35,0)
50699-03001-001-30P-L
  rect 0.229x0.787 smd: 1(-11.6,3.3) 2(-10.8,3.3) 3(-10,3.3) 4(-9.2,3.3) 5(-8.4,3.3) 6(-7.6,3.3) 7(-6.8,3.3) 8(-6,3.3) 9(-5.2,3.3) 10(-4.4,3.3) 11(-3.6,3.3) 12(-2.8,3.3) 13(-2,3.3) 14(-1.2,3.3) 15(-0.4,3.3) 16(0.4,3.3) 17(1.2,3.3) 18(2,3.3) 19(2.8,3.3) 20(3.6,3.3) 21(4.4,3.3) 22(5.2,3.3) 23(6,3.3) 24(6.8,3.3) 25(7.6,3.3) 26(8.4,3.3) 27(9.2,3.3) 28(10,3.3) 29(10.8,3.3) 30(11.6,3.3)
  rect 0.559x1.295 smd: 31(-13.075,0) 32(13.075,0)
88266-0200-2P-L
  rect 0.787x2.007 smd: 1(-0.625,2.725) 2(0.625,2.725)
  rect 2.007x2.489 smd: 3(-2.825,-1.325) 4(2.825,-1.325)
88460-08XX-8P-L
  rect 0.508x0.991 smd: 1(-2.8,1.95) 2(-2,1.95) 3(-1.2,1.95) 4(-0.4,1.95) 5(0.4,1.95) 6(1.2,1.95) 7(2,1.95) 8(2.8,1.95)
  rect 1.194x1.702 smd: 9(-4.1,0) 10(4.1,0)
88513-0601-6P-L-SMT
  rect 0.508x1.6 smd: 1(-2.5,2.95) 2(-1.5,2.95) 3(-0.5,2.95) 4(0.5,2.95) 5(1.5,2.95) 6(2.5,2.95)
  rect 1.803x1.397 smd: 7(-4.65,0) 8(4.65,0)
88513-0801-8P-L
  rect 0.508x1.295 smd: 1(-3.5,0) 2(-2.5,0) 3(-1.5,0) 4(-0.5,0) 5(0.5,0) 6(1.5,0) 7(2.5,0) 8(3.5,0)
  rect 1.803x1.397 smd: 9(-5.65,-2.8) 10(5.65,-2.8)
91504-0401-4P-L
  rect 0.508x1.295 smd: 1(-1.2,3.05) 2(-0.4,3.05) 3(0.4,3.05) 4(1.2,3.05)
  rect 1.803x1.905 smd: 5(-3.5,0) 6(3.5,0)
BAT-AP-AAA-BAT-046-2P
  round 1.092 hole 1.092 unplated: (0,4)
  round 0.711 hole 0.711 unplated: (0,-4)
  rect 2.007x1.499 smd: 1(7.4,0) 2(-7.4,0)
BGA96-MICRON-MT41K512M16
  round 0.356 smd: A1(-3.2,6) A2(-2.4,6) A3(-1.6,6) A7(1.6,6) A8(2.4,6) A9(3.2,6) B1(-3.2,5.2) B2(-2.4,5.2) B3(-1.6,5.2) B7(1.6,5.2) B8(2.4,5.2) B9(3.2,5.2) C1(-3.2,4.4) C2(-2.4,4.4) C3(-1.6,4.4) C7(1.6,4.4) C8(2.4,4.4) C9(3.2,4.4) D1(-3.2,3.6) D2(-2.4,3.6) D3(-1.6,3.6) D7(1.6,3.6) D8(2.4,3.6) D9(3.2,3.6) E1(-3.2,2.8) E2(-2.4,2.8) E3(-1.6,2.8) E7(1.6,2.8) E8(2.4,2.8) E9(3.2,2.8) F1(-3.2,2) F2(-2.4,2) F3(-1.6,2) F7(1.6,2) F8(2.4,2) F9(3.2,2) G1(-3.2,1.2) G2(-2.4,1.2) G3(-1.6,1.2) G7(1.6,1.2) G8(2.4,1.2) G9(3.2,1.2) H1(-3.2,0.4) H2(-2.4,0.4) H3(-1.6,0.4) H7(1.6,0.4) H8(2.4,0.4) H9(3.2,0.4) J1(-3.2,-0.4) J2(-2.4,-0.4) J3(-1.6,-0.4) J7(1.6,-0.4) J8(2.4,-0.4) J9(3.2,-0.4) K1(-3.2,-1.2) K2(-2.4,-1.2) K3(-1.6,-1.2) K7(1.6,-1.2) K8(2.4,-1.2) K9(3.2,-1.2) L1(-3.2,-2) L2(-2.4,-2) L3(-1.6,-2) L7(1.6,-2) L8(2.4,-2) L9(3.2,-2) M1(-3.2,-2.8) M2(-2.4,-2.8) M3(-1.6,-2.8) M7(1.6,-2.8) M8(2.4,-2.8) M9(3.2,-2.8) N1(-3.2,-3.6) N2(-2.4,-3.6) N3(-1.6,-3.6) N7(1.6,-3.6) N8(2.4,-3.6) N9(3.2,-3.6) P1(-3.2,-4.4) P2(-2.4,-4.4) P3(-1.6,-4.4) P7(1.6,-4.4) P8(2.4,-4.4) P9(3.2,-4.4) R1(-3.2,-5.2) R2(-2.4,-5.2) R3(-1.6,-5.2) R7(1.6,-5.2) R8(2.4,-5.2) R9(3.2,-5.2) T1(-3.2,-6) T2(-2.4,-6) T3(-1.6,-6) T7(1.6,-6) T8(2.4,-6) T9(3.2,-6)
